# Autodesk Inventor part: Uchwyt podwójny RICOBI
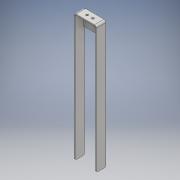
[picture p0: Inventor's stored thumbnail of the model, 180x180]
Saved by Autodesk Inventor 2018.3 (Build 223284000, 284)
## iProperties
Created: 2021-05
Part Number: Uchwyt podwójny RICOBI
Material: Ogólny
Document SubType Name: Modeling
Designer: Verical
Density: 1 g/cm^3
Appearance: Domyślna
Author: Verical
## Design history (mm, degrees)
derived "Uchwyt podwójny RICOBI.iam"
node "Bryła1"
node "Uchwyt podwójny.ipt:1"
node "Kapselek.ipt:1"
node "Kapselek.ipt:2"
node "Blaszka 64x40.ipt:1"
